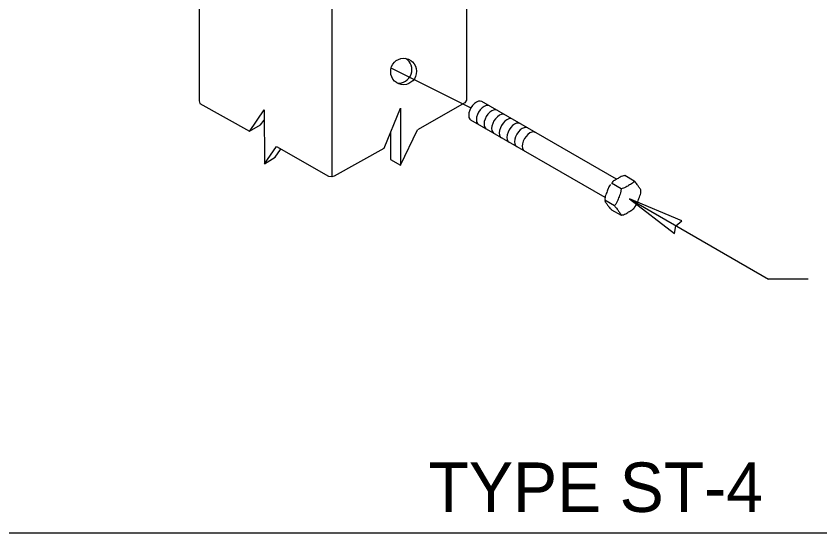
# Model space of a CAD drawing. Extents: x 99862 to 103680, y 99470 to 102076.
# Drawn here: x 101983.5 to 102308.6, y 99999.5 to 100208.5 of the extents above; entities that cross this region are included whole.
import ezdxf

# ---------------------------------------------------------------- set-up
doc = ezdxf.new("R2010")
doc.units = 0
for name, color, linetype in [('Level 1', 7, 'Continuous'), ('Level 13', 7, 'Continuous'), ('Level 15', 7, 'Continuous'), ('Level 20', 7, 'Continuous'), ('Level 3', 7, 'Continuous')]:
    doc.layers.add(name, color=color, linetype=linetype)

msp = doc.modelspace()

# ---------------------------------------------------------------- linework, layer by layer
at = {"layer": 'Level 1'}
msp.add_lwpolyline([(99862, 99999.5), (103151, 99999.5), (103151, 102075.5), (99862, 102075.5)], close=True, dxfattribs=at)
at = {"layer": 'Level 13'}
for p, q in [((102226.3, 100142.49), (102171.83, 100173.93)), ((102221.68, 100135.06), (102167.46, 100166.36)), ((102233.49, 100141.73), (102229.62, 100143.96)), ((102228.13, 100138.64), (102224.27, 100140.87)), ((102225.46, 100131.74), (102221.59, 100133.97)), ((102224.27, 100130.17), (102228.13, 100127.94))]:
    msp.add_line(p, q, dxfattribs=at)
for centre, start_param, end_param in [((102169.65, 100170.15), 6.283173, 9.424785), ((102172.74, 100168.36), 6.283174, 9.424783), ((102175.83, 100166.58), 6.283172, 9.424785), ((102178.92, 100164.79), 6.283179, 9.424784), ((102182.01, 100163.01), 6.283177, 9.424782), ((102185.11, 100161.22), 6.283174, 9.424785), ((102188.2, 100159.44), 6.283176, 9.424783), ((102191.29, 100157.65), 6.283178, 9.42478)]:
    msp.add_ellipse(centre, major_axis=(2.19, 3.78), ratio=0.57735, start_param=start_param, end_param=end_param, dxfattribs=at)
for points, degree in [([(102229.62, 100143.96), (102229.43, 100143.94), (102229.23, 100143.89), (102228.14, 100143.59), (102227.29, 100143.06), (102226.56, 100142.64), (102225.84, 100142.22), (102224.95, 100141.74), (102224.49, 100141.22)], 3), ([(102233.49, 100141.73), (102233.45, 100141.62), (102233.37, 100141.51), (102232.84, 100140.87), (102231.93, 100140.39), (102231.19, 100139.97), (102230.46, 100139.54), (102229.62, 100139.02), (102228.52, 100138.71), (102228.33, 100138.67), (102228.13, 100138.64)], 3), ([(102236.17, 100137.98), (102236.17, 100138.02), (102236.16, 100138.05), (102236.05, 100138.44), (102235.57, 100139.09), (102235.21, 100139.61), (102234.84, 100140.13), (102234.44, 100140.73), (102233.75, 100141.47), (102233.62, 100141.61), (102233.49, 100141.73)], 3), ([(102223.85, 100140.42), (102223.29, 100139.67), (102222.9, 100138.56), (102222.55, 100137.65), (102222.18, 100136.7), (102221.71, 100135.59), (102221.6, 100134.48), (102221.59, 100134.38), (102221.59, 100134.29)], 3), ([(102228.13, 100138.64), (102228.15, 100138.45), (102228.14, 100138.24), (102228.02, 100137.02), (102227.55, 100135.91), (102227.18, 100134.97), (102226.81, 100134.03), (102226.41, 100132.88), (102225.72, 100131.99), (102225.59, 100131.85), (102225.46, 100131.74)], 3), ([(102233.91, 100131.48), (102234.46, 100132.23), (102234.85, 100133.34), (102235.21, 100134.25), (102235.57, 100135.2), (102236.05, 100136.31), (102236.16, 100137.42), (102236.17, 100137.51), (102236.17, 100137.61)], 3), ([(102236.17, 100137.61), (102236.18, 100137.72), (102236.18, 100137.83), (102236.17, 100137.95), (102236.17, 100137.97), (102236.17, 100137.98)], 3), ([(102221.59, 100133.91), (102221.59, 100133.88), (102221.59, 100133.85), (102221.71, 100133.46), (102222.18, 100132.81), (102222.55, 100132.29), (102222.91, 100131.77), (102223.32, 100131.17), (102224.01, 100130.43), (102224.14, 100130.29), (102224.27, 100130.17)], 3), ([(102225.46, 100131.74), (102225.59, 100131.62), (102225.72, 100131.48), (102226.41, 100130.74), (102226.81, 100130.14), (102227.18, 100129.62), (102227.55, 100129.1), (102228.02, 100128.46), (102228.14, 100128.04), (102228.15, 100127.98), (102228.13, 100127.94)], 3), ([(102228.13, 100127.94), (102228.33, 100127.96), (102228.52, 100128), (102229.62, 100128.31), (102230.46, 100128.84), (102231.19, 100129.26), (102231.91, 100129.68), (102232.81, 100130.15), (102233.27, 100130.68)], 3), ([(102233.27, 100130.68), (102233.49, 100130.94), (102233.71, 100131.21), (102233.91, 100131.48)], 2)]:
    msp.add_open_spline(points, degree=degree, dxfattribs=at)
at = {"layer": 'Level 15'}
for p, q in [((102135.28, 100187.36), (102167.46, 100171.41)), ((102231.5, 100134.53), (102287.79, 100102.03)), ((102303.79, 100102.03), (102287.79, 100102.03))]:
    msp.add_line(p, q, dxfattribs=at)
msp.add_lwpolyline([(102231.5, 100134.53), (102249.78, 100120.53), (102250.35, 100123.64), (102252.76, 100125.7)], close=True, dxfattribs=at)
at = {"layer": 'Level 3'}
msp.add_line((102111.34, 100143.62), (102111.34, 100390.87), dxfattribs=at)
for points in [[(102057.53, 100421.63), (102057.53, 100174.24)], [(102165.59, 100343.99), (102165.59, 100174.54)], [(102057.53, 100174.24), (102057.53, 100174.15), (102057.81, 100173.18), (102077.97, 100161.94)], [(102165.59, 100174.54), (102165.59, 100174.43), (102165.02, 100173.45), (102145.85, 100162.49)], [(102111.2, 100143.62), (102112.34, 100143.9), (102132.36, 100155), (102139.03, 100171.23), (102139.03, 100148.2), (102145.85, 100162.49)], [(102077.97, 100161.8), (102083.8, 100170.54), (102083.94, 100148.76), (102088.77, 100155.69), (102109.92, 100143.76), (102111.34, 100143.62)], [(102077.97, 100161.94), (102082.38, 100164.44), (102083.8, 100166.38)], [(102134.91, 100161.24), (102134.91, 100150.42), (102139.03, 100148.2)], [(102083.94, 100148.76), (102088.34, 100151.39), (102090.47, 100154.58)]]:
    msp.add_lwpolyline(points, dxfattribs=at)
msp.add_ellipse((102140.21, 100186.06), major_axis=(-0.95, -5.27), ratio=0.972281, dxfattribs=at)
msp.add_ellipse((102138.36, 100186.74), major_axis=(-0.95, -5.27), ratio=0.972281, start_param=0.021287, end_param=2.783374, dxfattribs=at)

# ---------------------------------------------------------------- texts
at = {"layer": 'Level 20'}
msp.add_text('TYPE ST-4', height=20, dxfattribs=at).set_placement((102150.3, 100007.98))

doc.saveas('drawing.dxf')
